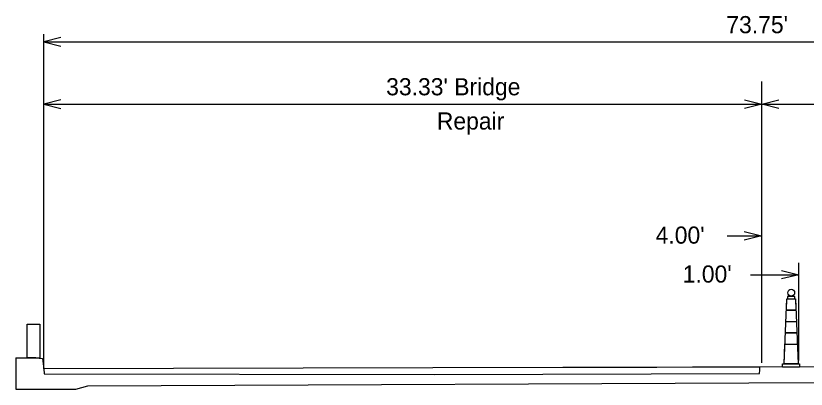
# Model space of a CAD drawing. Extents: x 8771 to 81668, y 6145 to 11018.
# Drawn here: x 10684 to 11732, y 6984 to 7479 of the extents above; entities that cross this region are included whole.
import ezdxf

# ---------------------------------------------------------------- set-up
doc = ezdxf.new("R2010")
doc.units = 0
for name, color, linetype in [('dsnCellElements', 7, 'Continuous'), ('DsnShtRevisedText', 7, 'Continuous'), ('Level 8', 7, 'Continuous'), ('ShtPlotIdentification', 7, 'Continuous')]:
    doc.layers.add(name, color=color, linetype=linetype)

msp = doc.modelspace()

# ---------------------------------------------------------------- linework, layer by layer
at = {"layer": 'dsnCellElements'}
for p, q in [((10720.7, 7010.8), (10720.7, 7454.4)), ((10720.7, 7444.3), (12624.9, 7444.3)), ((11672.8, 7018.8), (11672.8, 7391.8)), ((10720.7, 7361.6), (11672.8, 7361.6)), ((10879.4, 7361.6), (11672.8, 7361.6)), ((11672.8, 7361.6), (12624.9, 7361.6)), ((11626.9, 7187), (11672.3, 7187)), ((11721.9, 7022), (11721.9, 7151.4)), ((11657.8, 7135.7), (11721.8, 7135.7)), ((10710.2, 7025.6), (10698.8, 7025.6)), ((10715.4, 7025), (10710.2, 7025.6)), ((10779.4, 6988.4), (11752.9, 6992.6)), ((10763.2, 6983.9), (10779.4, 6988.4))]:
    msp.add_line(p, q, dxfattribs=at)
for points in [[(10743.4, 7450), (10720.7, 7444.3), (10743.4, 7438.7)], [(10743.4, 7367.3), (10720.7, 7361.6), (10743.4, 7355.9)], [(11650.1, 7367.3), (11672.8, 7361.6), (11650.1, 7355.9)], [(11695.5, 7355.9), (11672.8, 7361.6), (11695.5, 7367.3)], [(11649.6, 7192.7), (11672.3, 7187), (11649.6, 7181.3)], [(11699.1, 7141.4), (11721.8, 7135.7), (11699.1, 7130)], [(10698.8, 7025.6), (10698.8, 7070.1), (10715.4, 7070.1), (10715.4, 7025)], [(10683.7, 7025.6), (10683.7, 6983.9), (10763.2, 6983.9)], [(10683.7, 7025.6), (10710.2, 7025.6), (10719.2, 7024.6), (10720.7, 7010.8)]]:
    msp.add_lwpolyline(points, dxfattribs=at)
at = {"layer": 'DsnShtRevisedText'}
msp.add_lwpolyline([(10698.8, 7025.6), (10698.8, 7070.1), (10715.4, 7070.1), (10715.4, 7025)], dxfattribs=at)
at = {"layer": 'Level 8'}
for p, q in [((11702.4, 7017.5), (11706.2, 7103.7)), ((11705.5, 7088.7), (11706.2, 7103.7)), ((11706.2, 7103.7), (11717.4, 7103.7)), ((11706.2, 7103.7), (11717.4, 7103.7)), ((11717.4, 7103.7), (11721.2, 7017.5)), ((11717.4, 7103.7), (11718.1, 7088.7)), ((11705.5, 7088.7), (11718.1, 7088.7)), ((11718.1, 7088.7), (11705.5, 7088.7)), ((11704.2, 7058.7), (11704.8, 7073.7)), ((11704.8, 7073.7), (11718.7, 7073.7)), ((11704.8, 7073.7), (11718.7, 7073.7)), ((11718.7, 7073.7), (11719.4, 7058.7)), ((11704.2, 7058.7), (11719.4, 7058.7)), ((11719.4, 7058.7), (11704.2, 7058.7)), ((11702.4, 7017.5), (11703.5, 7043.7)), ((11703.5, 7043.7), (11720, 7043.7)), ((11703.5, 7043.7), (11720, 7043.7)), ((11720, 7043.7), (11721.2, 7017.5)), ((11700.5, 7017.5), (11723, 7017.5)), ((11700.5, 7013.7), (11700.5, 7017.5)), ((11700.5, 7013.7), (11723, 7013.7)), ((11721.2, 7017.5), (11702.4, 7017.5)), ((11723, 7017.5), (11723, 7013.7))]:
    msp.add_line(p, q, dxfattribs=at)
msp.add_lwpolyline([(11716.7, 7106.7), (11707.1, 7106.7), (11707.1, 7103.7), (11716.7, 7103.7)], close=True, dxfattribs=at)
msp.add_circle((11711.9, 7111.8), 4.5, dxfattribs=at)
at = {"layer": 'ShtPlotIdentification'}
for p, q in [((11752.9, 7013.5), (10720.7, 7010.8)), ((11239, 7003.5), (11670, 7004.8)), ((11670, 7004.8), (11670.1, 7009.3))]:
    msp.add_line(p, q, dxfattribs=at)
for points in [[(11236.8, 7012.1), (10720.7, 7010.8), (10721.3, 7004.5), (11239, 7003.5)], [(11670.1, 7009.3), (11670.1, 7013.3), (11658.1, 7013.2), (11639.6, 7013.2), (11613.6, 7013.1), (11580.8, 7013), (11533.7, 7012.9), (11468.4, 7012.7), (11434, 7012.6), (11236.8, 7012.1)]]:
    msp.add_lwpolyline(points, dxfattribs=at)

# ---------------------------------------------------------------- texts
at = {"layer": 'dsnCellElements'}
for s, height, p in [("73.75'", 22.71, (11625.8, 7455.7)), ("33.33' Bridge", 22.709, (11174.8, 7373.4)), ('Repair', 22.71, (11242, 7328)), ("4.00'", 22.71, (11532.1, 7176.8)), ("1.00'", 22.71, (11568, 7125.2))]:
    msp.add_text(s, height=height, dxfattribs=at).set_placement(p)

doc.saveas('drawing.dxf')
